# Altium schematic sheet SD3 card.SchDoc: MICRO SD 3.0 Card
size A4; DocumentNumber: MB1263; Revision: C-04; SheetNumber: 7; SheetTotal: 11; Project: STM32MP15-EVAL
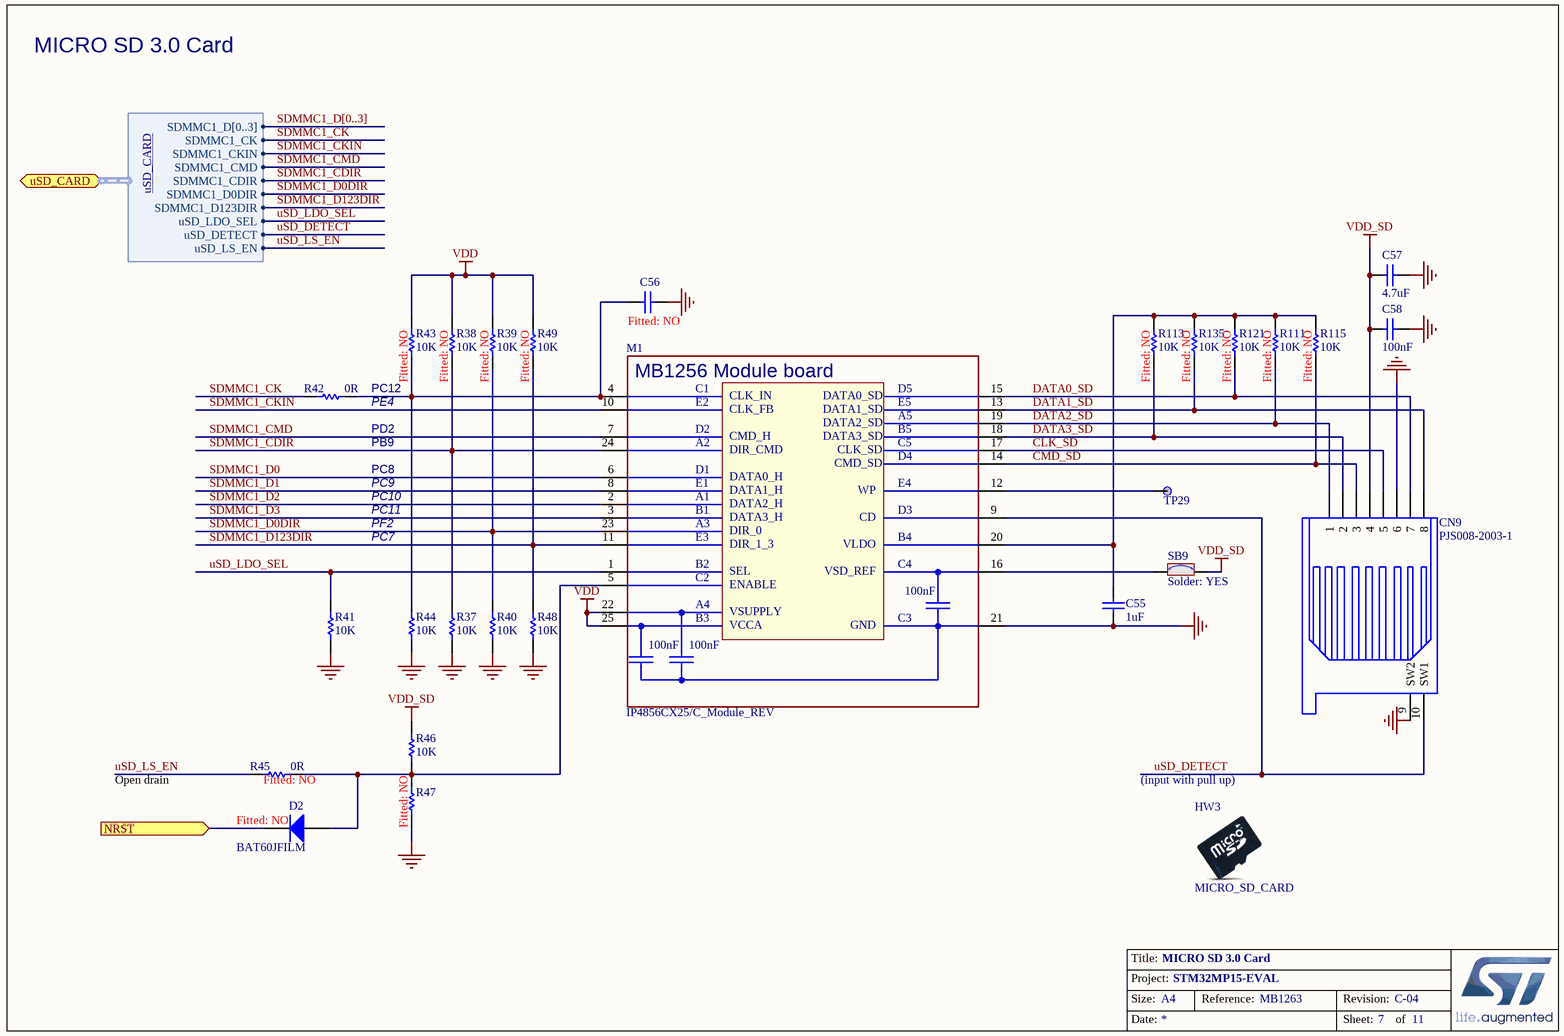
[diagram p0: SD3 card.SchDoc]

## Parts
C55  1uF  [C0603]
C56  Fitted: NO  [C0402]  (hidden comment: 100pF)
C57  4.7uF  [C0603]
C58  100nF  [C0402]
CN9  PJS008-2003-1  [CON_MICROSD_YAMAICHI_PJS008-2003-1]
D2  BAT60JFILM  Fitted: NO  [DIO_SOD323]
HW3  Micro_SD_card  (mechanical)
M1  IP4856CX25/C_Module_REV  [MOD_SD-CARD_8X8_MB1256]
R37  10K  [R0402]
R38  10K  Fitted: NO  [R0402]
R39  10K  Fitted: NO  [R0402]
R40  10K  [R0402]
R41  10K  [R0402]
R42  0R  [R0402]
R43  10K  Fitted: NO  [R0402]
R44  10K  [R0402]
R45  0R  Fitted: NO  [R0402]
R46  10K  [R0402]
R47  Fitted: NO  [R0402]  (hidden comment: 10K)
R48  10K  [R0402]
R49  10K  Fitted: NO  [R0402]
R111  10K  Fitted: NO  [R0402]
R113  10K  Fitted: NO  [R0402]
R115  10K  Fitted: NO  [R0402]
R121  10K  Fitted: NO  [R0402]
R135  10K  Fitted: NO  [R0402]
SB9  Solder: YES  [SOLDER-BRIDGE_R0603-0R]  (hidden comment: SB_ON)
TP29  TP  [TP_SMD_1MM]  (value not drawn)  (no BOM)

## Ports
NRST (in), uSD_CARD (harness uSD_CARD)

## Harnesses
uSD_CARD: SDMMC1_D[0..3], SDMMC1_CK, SDMMC1_CKIN, SDMMC1_CMD, SDMMC1_CDIR, SDMMC1_D0DIR, SDMMC1_D123DIR, uSD_LDO_SEL, uSD_DETECT, uSD_LS_EN

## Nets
GND: C55.1 C56.2 C57.2 C58.1 CN9.6 CN9.9(SW2) M1.21(WP) R37.1 R40.1 R41.1 R44.1 R47.1 R48.1
VDD: M1.22(CD) M1.25(GND) R38.2 R39.2 R43.2 R49.2
VDD_SD: C57.1 C58.2 CN9.4 R46.2 SB9.2
CLK_SD: CN9.5 M1.17(DATA2_SD)
CMD_SD: CN9.3 M1.14(VCCA) R115.1
DATA0_SD: CN9.7 M1.15(DATA0_SD) R121.1
DATA1_SD: CN9.8 M1.13(VSUPPLY) R135.1
DATA2_SD: CN9.1 M1.19(CLK_SD) R111.1
DATA3_SD: CN9.2 M1.18(DATA3_SD) R113.1
NRST: D2.2(K) ; port NRST
SDMMC1_CDIR: M1.24(VSD_REF) R37.2 R38.1 ; port uSD_CARD.SDMMC1_CDIR
SDMMC1_CK: R42.1 ; port uSD_CARD.SDMMC1_CK
SDMMC1_CKIN: M1.10(DIR_1_3) ; port uSD_CARD.SDMMC1_CKIN
SDMMC1_CMD: M1.7(DATA2_H) ; port uSD_CARD.SDMMC1_CMD
SDMMC1_D0: M1.6(DATA1_H)
SDMMC1_D0DIR: M1.23(VLDO) R39.1 R40.2 ; port uSD_CARD.SDMMC1_D0DIR
SDMMC1_D1: M1.8(DATA3_H)
SDMMC1_D2: M1.2(CLK_FB)
SDMMC1_D3: M1.3(CMD_H)
SDMMC1_D123DIR: M1.11(SEL) R48.2 R49.1 ; port uSD_CARD.SDMMC1_D123DIR
uSD_DETECT: CN9.10(SW1) M1.9(DIR_0) ; port uSD_CARD.uSD_DETECT
uSD_LDO_SEL: M1.1(CLK_IN) R41.2 ; port uSD_CARD.uSD_LDO_SEL
uSD_LS_EN: R45.1 ; port uSD_CARD.uSD_LS_EN
NetC55_2: C55.2 M1.20(CMD_SD) R111.2 R113.2 R115.2 R121.2 R135.2
NetC56_1: C56.1 M1.4(DIR_CMD) R42.2 R43.1 R44.2
NetD2_1: D2.1(A) M1.5(DATA0_H) R45.2 R46.1 R47.2
NetM1_12: M1.12(ENABLE) TP29.1
NetM1_16: M1.16(DATA1_SD) SB9.1

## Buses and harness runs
bus SDMMC1_D[0..3]

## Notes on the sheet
- MICRO SD 3.0 Card
- (near R42) PE4
- (near R42) PB9
- (near R42) PD2
- PC12
- PC8
- PC9
- PC10
- PC11
- PF2
- PC7
- Open drain
- (near HW3) (input with pull up)

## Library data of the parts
C55 = Cap_1uF_X5R_10%_0603: Capacitor,1uF,16V,X5R,10%,0603,YAGEO; Manuf_Part_1: CC0603KRX5R7BB105; Fitted: YES; Ordered_By: Subcon
C56 = Cap_100pF_NPO_5%_0402: Capacitor,100pF,50V,NPO,5%,0402,YAGEO; Order_Code: CC0402JRNPO9BN101; Ordered_By: Subcon
C57 = Cap_4.7uF_X5R_20%_0603_16V_MURATA: Capacitor MLCC 4,7uF 20% 16V 3uF@5V ESR=6mohm@100kHz  Z=20mohm@2MHz X5R 0603; Manuf_Part_1: GRM188R61C475MAAJ; Manuf_1: MURATA; Fitted: YES; Ordered_By: Subcon
C58 = Cap_100nF_X7R_10%_0402: Capacitor,100nF,16V,X7R,10%,0402,YAGEO; Manuf_Part_1: CC0402KRX7R7BB104; Fitted: YES; Ordered_By: Subcon
CN9 = microSD-PJS008-2003: Memory Card Connectors MicroSD Card Conn Revrs Mnt Push-Push; Manuf_1: YAMAICHI; Ordered_By: Subcon; Fitted: YES
D2 = BAT60JFILM: Manuf_1: STM; Ordered_By: Subcon; ECCN_US/EU: EAR99/NEC; Ref St: 9151097
HW3 = Micro_SD_card: MICRO_SD_CARD min 8GB class10; Manuf_1: Sandisk; Ordered_By: Subcon; Fitted: YES
M1 = IP4856CX25/C_Module_REV: SDcard3.0 dual voltage level  translator; Manuf_1: STM; Manuf_Part_1: MB1256; ECCN_US/EU: EAR99; Fitted: YES; Ordered_By: Subcon; Value: MB1256
R37 R40 R41 R44 R46 R48 = Res_10K_1%_0402: Resistor,10K,0402,1%,YAGEO; Manuf_Part_1: RC0402FR-0710KL; Order_Code: 9239359RL; Fitted: YES; Ordered_By: Subcon
R38 R39 R43 R47 R49 R111 R113 R115 R121 R135 = Res_10K_1%_0402: Resistor,10K,0402,1%,YAGEO; Manuf_Part_1: RC0402FR-0710KL; Order_Code: 9239359RL; Ordered_By: Subcon
R42 = Res_0_5%_0402: Resistor,0R,0402,5%,YAGEO; Manuf_Part_1: RC0402JR-070RL; Order_Code: 2363467; Fitted: YES; Ordered_By: Subcon
R45 = Res_0_5%_0402: Resistor,0R,0402,5%,YAGEO; Manuf_Part_1: RC0402JR-070RL; Order_Code: 2363467; Ordered_By: Subcon
SB9 = SB_ON: Solder Bridge ON; Ordered_by: Subcon
TP29 = TP 1mm: Test Point; Fitted: YES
